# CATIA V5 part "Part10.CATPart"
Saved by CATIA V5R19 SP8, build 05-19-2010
Part number: Cache
Bounding box of the stored display mesh (mm): x -234.228 to 565.772, y 480 to 500, z -564.104 to 35.896
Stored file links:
  G:\EU_thinkMotion\CFAO_2010\MMS_groupe1\MMS_groupe1\OK\ppiault\piault\piault_cfao\Part10.CATPart
  D:\Catia\Finaltest.CATProduct
  G:\Catia Projet\CFAO2\Product2.CATProduct
  G:\EU_thinkMotion\CFAO_2010\MMS_groupe1\MMS_groupe1\OK\ppiault\piault\piault_cfao\Part7.CATPart
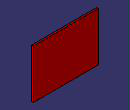
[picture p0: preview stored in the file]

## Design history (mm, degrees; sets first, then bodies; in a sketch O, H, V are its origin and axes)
External parameters (linked from other documents)
  External.DiametreRabatteur = 400 mm
  External.haut_axe = 195 mm
  External.bas_axe = 255 mm
Set1
  DatumSurface1: linked copy from another document
Body1 (main body)
  Sketch1 on DatumSurface1, origin (0, 500, 0), H (1, 0, 0), V (0, 0, 1)
    line L1 (-234.2277, -564.1043) -> (565.7723, -564.1043)
    line L2 (565.7723, -564.1043) -> (565.7723, 35.8957)
    line L3 (565.7723, 35.8957) -> (-234.2277, 35.8957)
    line L4 (-234.2277, 35.8957) -> (-234.2277, -564.1043)
    distance L1 L3 = 600 {= External.haut_axe  +External.bas_axe  +150mm}
    distance L2 L4 = 800 {= External.DiametreRabatteur *2}
    vertical: L2 V, L4 V
  Pad1: profile Sketch1, direction (0, -1, 0), length 20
